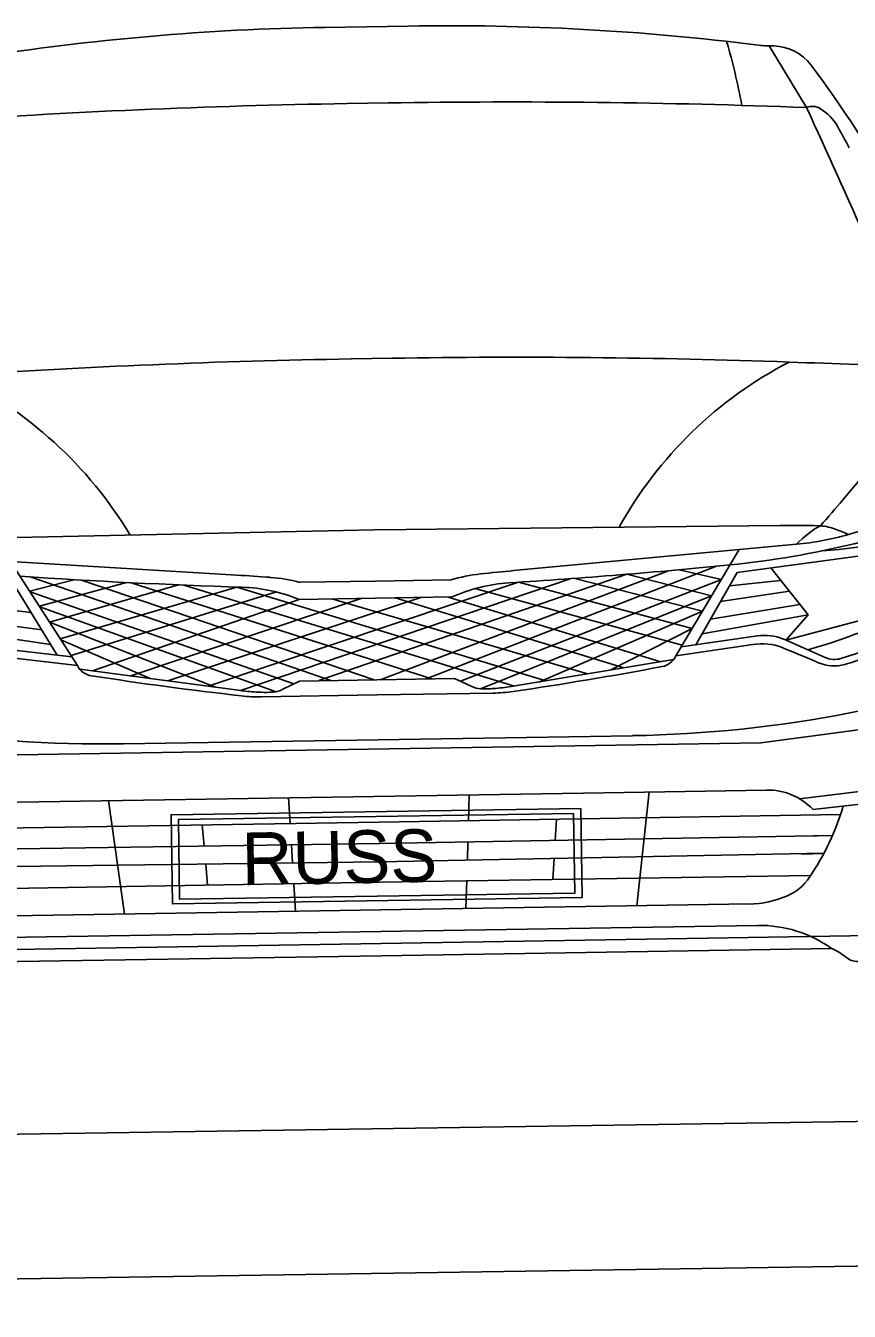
# Model space of a CAD drawing. Extents: x 10133 to 81668, y 4692 to 11018.
# Drawn here: x 11479.5 to 11560.8, y 8388.1 to 8515 of the extents above; entities that cross this region are included whole.
import ezdxf

# ---------------------------------------------------------------- set-up
doc = ezdxf.new("R2010")
doc.units = 0
for name, color, linetype in [('Cell', 7, 'Continuous'), ('Level 7', 7, 'Continuous'), ('SheetBorder', 7, 'Continuous')]:
    doc.layers.add(name, color=color, linetype=linetype)

msp = doc.modelspace()

# ---------------------------------------------------------------- linework, layer by layer
at = {"layer": 'Cell'}
for p, q in [((11552.88, 8512.99), (11556.55, 8506.91)), ((11570.23, 8480.18), (11560.13, 8468.18)), ((11549.92, 8463.26), (11527.64, 8461.19)), ((11500.34, 8460.74), (11478.01, 8462.1)), ((11542.94, 8461.18), (11514.49, 8450.42)), ((11547.66, 8461.62), (11519.02, 8450.5)), ((11556.71, 8456.82), (11553.02, 8461.47)), ((11484.26, 8460.29), (11479.91, 8459.15)), ((11479.94, 8460.56), (11509.62, 8450.34)), ((11489.46, 8460.01), (11480.86, 8457.67)), ((11485.02, 8460.25), (11513.87, 8450.41)), ((11489.9, 8459.99), (11519.59, 8450.51)), ((11495.09, 8459.76), (11527.73, 8449.79)), ((11533.23, 8460.39), (11500.68, 8449.35)), ((11548.95, 8459.69), (11554, 8460.23)), ((11479.94, 8459.1), (11505.97, 8450.02)), ((11504.25, 8459.08), (11483.97, 8452.82)), ((11512.6, 8458.44), (11489.88, 8450.79)), ((11518.5, 8458.54), (11493.54, 8450.3)), ((11515.96, 8458.5), (11538.54, 8451.6)), ((11521.19, 8458.58), (11542.17, 8452.2)), ((11523.83, 8459.41), (11544.29, 8453.84)), ((11548.07, 8458.14), (11554.86, 8459.15)), ((11480.03, 8457.04), (11473.2, 8457.83)), ((11480.9, 8457.6), (11504.23, 8449.23)), ((11506.49, 8458.35), (11486.09, 8451.3)), ((11509.7, 8458.4), (11534.93, 8450.99)), ((11547.07, 8456.4), (11555.88, 8457.86)), ((11481.08, 8455.33), (11472.22, 8456.51)), ((11556.7, 8456.84), (11546.24, 8454.95)), ((11471.44, 8455.46), (11481.96, 8453.91)), ((11544.19, 8453.66), (11551.7, 8454.75)), ((11484.05, 8452.69), (11476.51, 8453.54)), ((11482.98, 8454.36), (11491.77, 8450.54)), ((11551.26, 8453.9), (11543.65, 8452.77)), ((11554.25, 8454.44), (11558.38, 8452.61)), ((11476.98, 8452.7), (11484.62, 8451.81)), ((11543.44, 8452.41), (11527.61, 8449.77)), ((11500.74, 8449.34), (11484.84, 8451.47)), ((11572.6, 8446.89), (11552.04, 8444.2)), ((11489.14, 8444.08), (11539.37, 8444.89)), ((11476.51, 8442.98), (11552.04, 8444.2)), ((11534.53, 8439.23), (11552.59, 8439.52)), ((11555.86, 8438.66), (11572.16, 8440.64)), ((11534.53, 8439.23), (11476.11, 8438.29)), ((11487.68, 8438.48), (11489.25, 8427.28)), ((11505.44, 8438.76), (11505.59, 8436.23)), ((11523.26, 8439.05), (11523.19, 8436.51)), ((11541.01, 8439.34), (11539.82, 8428.1)), ((11496.91, 8436.09), (11497.1, 8433.99)), ((11531.87, 8436.65), (11531.75, 8434.55)), ((11523.13, 8434.4), (11523.08, 8432.6)), ((11556.12, 8434.98), (11559.1, 8435.03)), ((11505.72, 8434.12), (11505.83, 8432.33)), ((11556.06, 8433.21), (11558.25, 8433.25)), ((11497.26, 8432.22), (11497.45, 8430.13)), ((11531.64, 8432.77), (11531.52, 8430.68)), ((11523.02, 8430.55), (11522.94, 8427.82)), ((11554.94, 8431.05), (11556.96, 8431.08)), ((11505.95, 8430.28), (11506.12, 8427.55)), ((11514.6, 8423.17), (11470.18, 8422.45)), ((11559.02, 8423.89), (11514.6, 8423.17))]:
    msp.add_line(p, q, dxfattribs=at)
for points in [[(11509.01, 8514.82), (11513.12, 8514.89), (11517.24, 8514.96)], [(11515.26, 8507.37), (11513.24, 8507.33), (11511.23, 8507.3)], [(11515.67, 8482.16), (11513.65, 8482.13), (11511.63, 8482.1)], [(11473.91, 8464.36), (11513.92, 8465.23), (11553.95, 8465.65)], [(11543.65, 8452.77), (11549.92, 8463.26), (11555.58, 8463.79)], [(11545.62, 8453.87), (11549.71, 8461.02), (11569.9, 8463.75), (11571.06, 8464.09)], [(11482.61, 8452.85), (11478.29, 8459.87), (11458.02, 8461.95), (11456.86, 8462.24)], [(11472.34, 8462.45), (11478.01, 8462.1), (11484.62, 8451.81)], [(11543.97, 8461.27), (11548.15, 8460.31), (11522.42, 8450.26)], [(11494.59, 8459.78), (11481.86, 8456.1), (11498.22, 8449.68)], [(11537.23, 8451.38), (11545.26, 8455.47), (11528.14, 8460.04), (11497.52, 8449.77)], [(11521.45, 8460.28), (11514.01, 8460.16), (11506.57, 8460.04)], [(11524.37, 8449.52), (11547.19, 8458.7), (11538.82, 8460.83), (11508.44, 8450.33)], [(11533.69, 8460.42), (11546.29, 8457.19), (11530.14, 8450.19)], [(11530.82, 8450.31), (11500.32, 8459.57), (11482.91, 8454.47)], [(11506.49, 8458.35), (11514.03, 8458.47), (11521.58, 8458.59)], [(11562.58, 8456.45), (11554.51, 8454.33), (11556.71, 8456.82)], [(11523.47, 8449.77), (11521.81, 8450.54), (11514.16, 8450.42), (11506.51, 8450.29), (11504.88, 8449.47)], [(11502.76, 8448.73), (11514.19, 8448.91), (11525.62, 8449.1)], [(11557.16, 8437.62), (11570.66, 8439.11), (11570.87, 8434.27)], [(11559.9, 8437.1), (11514.39, 8436.37), (11468.88, 8435.63)], [(11469.74, 8433.6), (11514.42, 8434.24), (11559.11, 8435.05)], [(11470.64, 8431.87), (11514.45, 8432.44), (11558.27, 8433.29)], [(11472.02, 8429.7), (11514.49, 8430.42), (11556.95, 8431.08)], [(11478.16, 8427.1), (11514.53, 8427.69), (11550.9, 8428.28)], [(11477.41, 8424.96), (11514.56, 8425.56), (11551.72, 8426.16)], [(11466.3, 8423.59), (11514.58, 8424.37), (11562.87, 8425.15)]]:
    msp.add_lwpolyline(points, dxfattribs=at)
for centre, radius, start, end in [((11512.96, 8269.9), 244.96, 90.9252, 99.032), ((11521.19, 8270.03), 244.96, 82.8184, 90.9252), ((11488.83, 8495.93), 62.35, 10.3492, 16.3142), ((11553.05, 8522.83), 9.84, 262.8184, 271.6449), ((11553.23, 8508.27), 4.72, 37.2049, 88.7843), ((11462.81, 8440.83), 117.52, 29.1906, 36.7399), ((11523.51, 7746.65), 760.75, 90.92522, 94.03496), ((11527.55, 7746.71), 760.75, 87.81549, 90.92522), ((11557.12, 8505.52), 1.51, 59.6358, 112.2665), ((10672.55, 8099.72), 973.27, 23.86415, 24.73223), ((11555.46, 8502.7), 4.77, 29.0579, 59.6358), ((11396.78, 8414.53), 186.3, 28.3313, 29.0579), ((11523.92, 7721.44), 760.75, 90.92522, 93.87552), ((11527.95, 7721.51), 760.75, 87.97493, 90.92522), ((11573.49, 8445.81), 40.52, 117.404, 150.9552), ((11614.18, 10160.09), 1679.36, 267.97493, 268.43668), ((11455.02, 8443.9), 40.52, 30.8952, 64.4465), ((11520.4, 8604.13), 145.07, 286.1237, 291.1423), ((11540.29, 8549.9), 88.57, 275.6502, 291.7495), ((11468.01, 8545.65), 120.37, 318.3262, 319.9365), ((11555.04, 8363.18), 102.48, 88.4825, 90.611), ((11562.42, 8457.42), 9.35, 118.7421, 137.0218), ((11557.62, 8460.75), 4.87, 69.7987, 88.4825), ((11549.15, 8565.43), 102.69, 275.0255, 282.1177), ((11552.33, 8446.37), 20.2, 65.5678, 69.7987), ((11553, 8491.36), 27.69, 275.3319, 286.111), ((11558.61, 8129.39), 333.24, 95.3319, 95.897), ((11487.35, 9085.05), 626.34, 273.6469, 275.65017), ((11520.47, 9085.59), 626.34, 266.20028, 268.20355), ((11480.11, 8128.12), 333.24, 85.9535, 86.5185), ((11502.51, 8444.78), 15.78, 75.1008, 85.9535), ((11526, 8445.16), 15.78, 95.897, 106.7496), ((11528.22, 8443.77), 16.24, 93.6469, 114.1364), ((11500.33, 8443.32), 16.24, 67.7141, 88.2036), ((11539.03, 8514.82), 63.94, 286.0198, 297.5669), ((11551.37, 8482.04), 30.75, 286.1878, 308.9768), ((11552.4, 8449.91), 4.89, 67.7355, 98.2527), ((11552.15, 8448.56), 5.41, 68.4241, 99.49), ((11516.89, 8359.41), 101.28, 66.2125, 68.4241), ((11547.75, 8493.56), 43.5, 286.8181, 293.0038), ((11537.43, 8566.95), 122.07, 270.9123, 291.1957), ((11541.97, 8453.53), 1.85, 280.6763, 335.5222), ((11559.28, 8455.75), 3.97, 247.2251, 285.4521), ((11559.31, 8454.7), 2.28, 246.1416, 286.1878), ((11487.14, 8566.14), 122.07, 250.6548, 270.9382), ((11486.27, 8452.63), 1.85, 206.3282, 261.1741), ((11541.18, 8806.26), 359.71, 261.1741, 263.5504), ((11475.67, 8805.2), 359.71, 278.3001, 280.6763), ((11524.5, 8451.74), 2.22, 242.4389, 268.5867), ((11524.79, 8463.61), 14.09, 268.5867, 274.5358), ((11524.33, 8469.41), 19.91, 274.5358, 279.4823), ((11503.39, 8469.07), 19.91, 262.3681, 267.3147), ((11502.51, 8464.15), 15.43, 263.5504, 270.9252), ((11503.11, 8463.26), 14.09, 267.3147, 273.2637), ((11503.79, 8451.41), 2.22, 273.2637, 299.4115), ((11525.37, 8464.52), 15.43, 270.9252, 278.3001), ((11552.69, 8433.31), 6.22, 43.9718, 90.9252), ((11535.72, 8445.17), 25.49, 325.9869, 343.5575), ((11552.62, 8433.76), 5.1, 293.5953, 325.9869), ((11550.74, 8438.07), 9.8, 270.9252, 293.5953), ((11551.92, 8413.91), 12.25, 54.5491, 90.9252), ((11557.4, 8419.63), 4.55, 48.6877, 69.1557), ((11561.64, 8424.45), 1.86, 228.6877, 270.9252)]:
    msp.add_arc(centre, radius, start, end, dxfattribs=at)
at = {"layer": 'Level 7'}
for p, q in [((11264.61, 8402.34), (11700.03, 8408.87)), ((11264.61, 8388.06), (11700.03, 8394.59))]:
    msp.add_line(p, q, dxfattribs=at)
at = {"layer": 'SheetBorder'}
for points in [[(11534.27, 8437.71), (11493.84, 8437.09), (11493.97, 8428.29), (11534.4, 8428.91)], [(11533.56, 8437.22), (11494.56, 8436.62), (11494.68, 8428.74), (11533.68, 8429.34)]]:
    msp.add_lwpolyline(points, close=True, dxfattribs=at)

# ---------------------------------------------------------------- texts
msp.add_text('RUSS', height=5.197, rotation=1.1069, dxfattribs=at).set_placement((11500.85, 8430.12))

doc.saveas('drawing.dxf')
